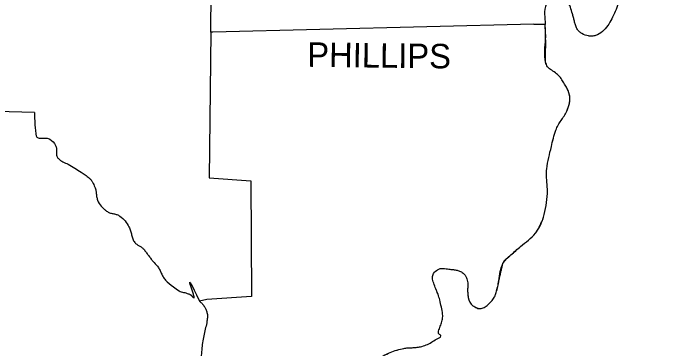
# Model space of a CAD drawing. Extents: x -33639 to 34530, y -17264 to 5867.
# Drawn here: x 3591 to 4217, y -9022 to -8698 of the extents above; entities that cross this region are included whole.
import ezdxf

# ---------------------------------------------------------------- set-up
doc = ezdxf.new("R2010")
doc.units = 0
for name, color, linetype in [('1', 7, 'Continuous'), ('2', 7, 'Continuous'), ('S_MISC_BOUNDARY', 7, 'Continuous')]:
    doc.layers.add(name, color=color, linetype=linetype)

msp = doc.modelspace()

# ---------------------------------------------------------------- linework, layer by layer
at = {"layer": '1'}
for points in [[(3782.6552624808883, -8716.897825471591), (3783.4401276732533, -8638.999955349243), (3748.7678360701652, -8634.046770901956), (3747.6671284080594, -8487.102296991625), (4217.118949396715, -8483.800173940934)], [(3612.280085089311, -8794.199736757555), (3404.2463354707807, -8788.696198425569), (3403.1456278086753, -8856.389720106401), (2982.1249442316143, -8858.04078158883)]]:
    msp.add_lwpolyline(points, dxfattribs=at)
for points in [[(4182.446657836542, -8616.985801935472), (4176.839301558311, -8626.142518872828), (4173.354075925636, -8629.968216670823), (4169.788519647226, -8632.946063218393), (4159.607709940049, -8631.900198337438), (4154.44128474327, -8628.02159438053), (4152.446856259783, -8625.615408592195), (4151.076489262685, -8623.03969419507), (4150.282008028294, -8616.424934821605), (4151.076489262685, -8609.831202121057), (4151.769537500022, -8606.379750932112), (4152.792009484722, -8602.937733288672), (4153.644663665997, -8599.502738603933), (4153.828258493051, -8596.072356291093), (4151.446090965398, -8591.104456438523), (4149.384231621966, -8589.015564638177), (4147.224012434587, -8587.266694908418), (4144.204489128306, -8586.327332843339), (4140.520775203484, -8586.809036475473), (4137.299322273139, -8588.48268852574), (4135.666581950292, -8591.119171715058), (4135.351394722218, -8595.382917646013), (4135.47434529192, -8599.651441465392), (4135.693414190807, -8603.91907265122), (4135.666581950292, -8608.180140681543), (4134.565874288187, -8624.690755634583), (4133.752950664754, -8630.63622680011), (4132.550640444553, -8636.557368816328), (4131.267171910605, -8645.409490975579), (4131.228518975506, -8646.882861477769), (4131.2637512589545, -8648.355970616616), (4133.887594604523, -8652.852424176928), (4136.332989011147, -8654.454435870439), (4138.968704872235, -8655.510570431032), (4143.361232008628, -8656.416362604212), (4147.778591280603, -8656.835997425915), (4152.193838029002, -8657.143272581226), (4156.58002759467, -8657.711985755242), (4162.965734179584, -8658.792122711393), (4166.118202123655, -8659.628099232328), (4169.238165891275, -8661.014108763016), (4174.468412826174, -8666.511939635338), (4175.971373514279, -8670.016217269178), (4176.943119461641, -8673.672246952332), (4177.608761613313, -8681.424923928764), (4176.3927656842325, -8689.082154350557), (4170.338873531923, -8703.941707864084), (4161.533212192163, -8716.049492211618), (4154.802060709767, -8719.895896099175), (4151.207795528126, -8720.602523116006), (4147.774366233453, -8720.452322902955), (4141.606295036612, -8718.156427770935), (4138.855503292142, -8716.05829140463), (4136.767289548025, -8713.29772308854), (4135.259610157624, -8709.733553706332), (4134.25795405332, -8706.134989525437), (4133.410258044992, -8702.540492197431), (4132.364458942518, -8698.98852337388), (4130.390589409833, -8692.638326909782), (4127.4112743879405, -8686.330385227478), (4125.205462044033, -8683.17621605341), (4122.843679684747, -8680.207531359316), (4118.055259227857, -8676.974369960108), (4115.508946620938, -8677.829001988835), (4112.959817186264, -8680.318819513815), (4110.481816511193, -8683.750592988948), (4109.292597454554, -8685.60307897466), (4108.148890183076, -8687.431092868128), (4105.482324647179, -8697.045322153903), (4105.9474748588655, -8706.693477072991), (4106.02163556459, -8709.30490390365)], [(3612.280085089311, -8794.199736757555), (3612.6459980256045, -8805.498155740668), (3613.095594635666, -8811.136475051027), (3613.4553670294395, -8813.951832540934), (3613.931146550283, -8816.764243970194), (3614.603640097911, -8818.08558149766), (3615.867074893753, -8818.786801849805), (3619.544067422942, -8819.049941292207), (3623.7167225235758, -8818.995762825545), (3625.5997355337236, -8819.30033579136), (3627.1396385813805, -8820.066366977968), (3632.6431769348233, -8826.120259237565), (3633.5182837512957, -8829.345532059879), (3633.4958907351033, -8832.984617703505), (3633.7350831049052, -8836.356058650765), (3635.3949460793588, -8838.778397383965), (3644.750961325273, -8844.281935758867), (3657.409099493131, -8851.986889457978), (3661.3475187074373, -8854.566361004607), (3663.2495329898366, -8855.972601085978), (3665.114053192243, -8857.490427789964), (3666.912376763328, -8859.397520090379), (3668.3419898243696, -8861.574758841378), (3669.533519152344, -8863.911247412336), (3670.6175915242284, -8866.29608917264), (3671.6601689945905, -8869.789880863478), (3672.154270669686, -8873.450711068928), (3672.705563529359, -8877.111530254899), (3673.9197145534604, -8880.6052888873), (3677.7374188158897, -8885.809518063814), (3680.1179015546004, -8887.990842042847), (3682.725375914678, -8889.961304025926), (3685.654498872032, -8891.328068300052), (3688.8388209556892, -8892.085290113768), (3691.993366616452, -8892.881226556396), (3694.8331603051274, -8894.364134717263), (3703.638821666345, -8904.820857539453), (3705.211449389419, -8908.482533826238), (3706.203943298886, -8912.412651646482), (3707.2897609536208, -8916.26176081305), (3709.1423599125, -8919.68041113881), (3711.155509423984, -8921.520623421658), (3713.5354468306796, -8922.99372230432), (3715.9202561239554, -8924.46122708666), (3717.948021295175, -8926.284657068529), (3720.172930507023, -8929.144806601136), (3722.3330942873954, -8932.073854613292), (3724.502136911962, -8934.997661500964), (3726.7536826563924, -8937.842087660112), (3731.1565133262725, -8942.795272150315), (3733.230450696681, -8945.98491689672), (3734.9033724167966, -8949.462593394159), (3736.629103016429, -8952.908732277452), (3738.861467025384, -8956.003764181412), (3746.5664207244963, -8962.608010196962), (3752.0699590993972, -8966.460487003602), (3754.171529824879, -8967.368614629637), (3756.4121827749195, -8967.94030184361), (3758.683139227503, -8968.460023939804), (3760.8756204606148, -8969.21225621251), (3763.8057252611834, -8970.656732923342), (3766.5940347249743, -8972.28962321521), (3771.8826971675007, -8976.366856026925), (3771.8826971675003, -8976.366856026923)]]:
    msp.add_spline(points, degree=3, dxfattribs=at)
at = {"layer": 'S_MISC_BOUNDARY'}
for p, q in [((4094.9403981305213, -8708.894892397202), (4106.02163556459, -8709.30490390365)), ((4106.02163556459, -8709.30490390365), (4094.9403981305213, -8708.894892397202))]:
    msp.add_line(p, q, dxfattribs=at)
for points in [[(4094.9403981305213, -8708.894892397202), (3784.540835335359, -8716.599846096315), (3782.6552624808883, -8716.897825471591), (3781.238712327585, -8857.490427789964), (3821.4145422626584, -8860.242196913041), (3821.9648961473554, -8971.964025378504), (3779.037296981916, -8974.715794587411), (3771.8826971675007, -8976.366856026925)], [(4094.9403981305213, -8708.894892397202), (3784.540835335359, -8716.599846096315), (3782.6552624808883, -8716.897825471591), (3781.238712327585, -8857.490427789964), (3821.4145422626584, -8860.242196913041), (3821.9648961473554, -8971.964025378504), (3779.037296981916, -8974.715794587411), (3771.8826971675, -8976.366856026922)]]:
    msp.add_lwpolyline(points, dxfattribs=at)
for points in [[(3865.99320288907, -9151.379375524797), (3867.4980547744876, -9147.874374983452), (3869.6105555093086, -9144.47649683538), (3875.899571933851, -9138.721237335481), (3880.8135846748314, -9136.348935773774), (3885.739313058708, -9134.996788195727), (3895.7123100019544, -9134.318406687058), (3899.839959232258, -9134.610621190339), (3903.9677854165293, -9135.171892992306), (3908.0955276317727, -9135.719187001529), (3912.2229249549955, -9135.969468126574), (3932.5860169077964, -9133.768052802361), (3939.797636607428, -9131.09677495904), (3943.123506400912, -9129.052991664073), (3946.34486273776, -9126.613452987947), (3950.65909664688, -9119.310034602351), (3950.8067185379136, -9115.17468012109), (3949.0966318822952, -9111.753899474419), (3945.9433337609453, -9108.80302774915), (3942.4726144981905, -9106.258528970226), (3938.736604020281, -9104.535477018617), (3934.7874322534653, -9104.048945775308), (3919.3775248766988, -9105.700007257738), (3903.417263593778, -9106.800714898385), (3895.6154853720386, -9105.634539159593), (3891.804334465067, -9104.19240677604), (3888.0073563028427, -9102.397884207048), (3877.5506333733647, -9093.041869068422), (3874.279775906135, -9085.173510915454), (3874.7988642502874, -9077.08160787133), (3876.1435894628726, -9073.610776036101), (3878.0124648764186, -9070.19105025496), (3880.4759553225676, -9067.46483411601), (3883.6045256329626, -9066.074531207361), (3885.5248064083, -9065.898640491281), (3887.45251670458, -9065.905292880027), (3891.3187711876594, -9066.31958270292), (3899.0144330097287, -9067.725592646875), (3910.5718634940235, -9069.927007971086), (3921.0285863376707, -9065.524177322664), (3928.733540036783, -9056.168162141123), (3937.5392013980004, -9046.2617931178), (3939.279349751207, -9043.417711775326), (3940.4859833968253, -9040.230734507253), (3941.7326990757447, -9037.032340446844), (3943.593093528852, -9034.15400872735), (3956.251231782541, -9025.898701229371), (3969.4597238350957, -9022.0462243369), (3973.414452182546, -9021.518812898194), (3977.4115903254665, -9021.325191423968), (3981.4228605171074, -9021.079321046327), (3985.4199850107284, -9020.395162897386), (3996.1110753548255, -9016.13839352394), (4000.9356181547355, -9013.205668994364), (4005.2327231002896, -9009.93843994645), (4005.197609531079, -9009.472691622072), (4004.4013825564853, -9008.983266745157), (4003.470472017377, -9008.42107463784), (4003.031307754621, -9007.73702462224), (4003.8208665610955, -9003.06332252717), (4005.362606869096, -8998.386437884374), (4006.70181682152, -8993.706839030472), (4006.8837845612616, -8989.024994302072), (4005.6561278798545, -8982.145199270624), (4004.132015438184, -8975.266148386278), (4002.4155369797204, -8969.79534489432), (4000.283165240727, -8964.433190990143), (3998.2865686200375, -8959.121565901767), (3996.977415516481, -8953.802348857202), (3998.1732886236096, -8949.603504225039), (4001.9306000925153, -8946.097395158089), (4004.6624243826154, -8944.950646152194), (4007.4315362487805, -8944.762386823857), (4012.9376767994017, -8945.547041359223), (4016.4440965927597, -8945.896448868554), (4019.9259854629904, -8946.34502339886), (4023.3534314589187, -8947.357726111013), (4026.6965226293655, -8949.399518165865), (4028.662449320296, -8951.482277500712), (4029.9242472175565, -8953.771031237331), (4031.099353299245, -8958.755533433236), (4031.222494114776, -8961.0920969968), (4031.1300157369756, -8963.435976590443), (4031.0222061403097, -8965.778638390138), (4031.099353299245, -8968.111548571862), (4033.300768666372, -8977.467563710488), (4039.9050146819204, -8982.97110208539), (4044.0860832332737, -8983.518702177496), (4048.160322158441, -8981.870394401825), (4051.661191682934, -8978.873916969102), (4054.7086362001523, -8975.63895027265), (4057.0961044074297, -8972.079994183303), (4058.617045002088, -8968.111548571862), (4061.3688142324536, -8956.55411806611), (4065.2212910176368, -8940.043503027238), (4072.926244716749, -8931.788195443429), (4082.282259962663, -8923.532887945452), (4096.591459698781, -8910.87474979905), (4104.296413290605, -8895.464842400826), (4106.84687790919, -8883.954113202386), (4108.148890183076, -8872.34998130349), (4108.102737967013, -8866.431359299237), (4107.626498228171, -8860.497021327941), (4107.27386600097, -8854.572859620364), (4107.598536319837, -8848.684766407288), (4112.001366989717, -8827.220966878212), (4116.404197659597, -8811.260705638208), (4118.531872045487, -8806.525237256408), (4121.351726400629, -8802.110190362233), (4124.311997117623, -8797.729981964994), (4126.860920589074, -8793.099029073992), (4129.61268973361, -8777.689121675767), (4126.120310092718, -8768.920323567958), (4123.551926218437, -8764.726733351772), (4120.807028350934, -8760.62815283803), (4116.998324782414, -8756.819163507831), (4112.402360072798, -8753.593945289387), (4108.431429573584, -8750.17094246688), (4106.497828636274, -8745.768599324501), (4106.497828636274, -8723.204092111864), (4106.02163556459, -8709.30490390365)], [(4103.473675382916, -8898.277130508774), (4104.296413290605, -8895.464842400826), (4105.761220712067, -8889.741818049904), (4106.84687790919, -8883.954113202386), (4108.148890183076, -8872.34998130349), (4108.102737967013, -8866.431359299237), (4107.626498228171, -8860.497021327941), (4107.27386600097, -8854.572859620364), (4107.598536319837, -8848.684766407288), (4112.001366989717, -8827.220966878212), (4116.404197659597, -8811.260705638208), (4118.531872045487, -8806.525237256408), (4121.351726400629, -8802.110190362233), (4124.311997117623, -8797.729981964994), (4126.860920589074, -8793.099029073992), (4129.475007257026, -8785.444568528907), (4129.924134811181, -8781.512814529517), (4129.61268973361, -8777.689121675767), (4128.249359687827, -8773.213239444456), (4126.120310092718, -8768.920323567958), (4123.551926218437, -8764.726733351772), (4120.807028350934, -8760.62815283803), (4116.998324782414, -8756.819163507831), (4112.402360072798, -8753.593945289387), (4108.431429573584, -8750.17094246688), (4106.497828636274, -8745.768599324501), (4106.4216027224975, -8740.127449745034), (4106.493967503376, -8734.485224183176), (4106.568262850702, -8728.84355938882), (4106.497828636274, -8723.204092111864), (4106.02163556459, -8709.30490390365)], [(4002.1590626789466, -8969.131808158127), (4000.283165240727, -8964.433190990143), (3998.2865686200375, -8959.121565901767), (3996.977415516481, -8953.802348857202), (3998.1732886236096, -8949.603504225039), (4001.9306000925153, -8946.097395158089), (4004.6624243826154, -8944.950646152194), (4007.4315362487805, -8944.762386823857), (4012.9376767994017, -8945.547041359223), (4016.4440965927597, -8945.896448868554), (4019.9259854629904, -8946.34502339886), (4023.3534314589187, -8947.357726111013), (4026.6965226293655, -8949.399518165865), (4028.662449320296, -8951.482277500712), (4029.9242472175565, -8953.771031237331), (4031.099353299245, -8958.755533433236), (4031.222494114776, -8961.0920969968), (4031.1300157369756, -8963.435976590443), (4031.0222061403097, -8965.778638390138), (4031.099353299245, -8968.111548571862), (4031.6919003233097, -8972.840224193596), (4032.3327610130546, -8975.16213644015), (4033.300768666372, -8977.467563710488), (4036.0799892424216, -8980.778076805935), (4037.8971230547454, -8981.968272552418), (4039.9050146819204, -8982.97110208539), (4042.0024122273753, -8983.579835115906), (4044.0860832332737, -8983.518702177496), (4048.160322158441, -8981.870394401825), (4051.661191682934, -8978.873916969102), (4054.7086362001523, -8975.63895027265), (4057.0961044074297, -8972.079994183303), (4058.617045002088, -8968.111548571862), (4061.3688142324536, -8956.55411806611), (4063.243446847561, -8948.293143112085), (4064.1946518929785, -8944.163363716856), (4064.695440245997, -8942.101750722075), (4065.2212910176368, -8940.043503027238), (4068.3754855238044, -8935.48055522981), (4072.926244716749, -8931.788195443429), (4082.282259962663, -8923.532887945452), (4096.591459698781, -8910.87474979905), (4103.473675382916, -8898.277130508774)], [(3875.073105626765, -9076.245004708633), (3876.1435894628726, -9073.610776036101), (3878.0124648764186, -9070.19105025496), (3880.4759553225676, -9067.46483411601), (3883.6045256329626, -9066.074531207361), (3885.5248064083, -9065.898640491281), (3887.45251670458, -9065.905292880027), (3891.3187711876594, -9066.31958270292), (3899.0144330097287, -9067.725592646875), (3910.5718634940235, -9069.927007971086), (3916.1613720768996, -9069.048075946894), (3918.7564375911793, -9067.512435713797), (3921.0285863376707, -9065.524177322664), (3923.1002419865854, -9063.20100068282), (3924.991004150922, -9060.84081452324), (3928.733540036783, -9056.168162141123), (3933.155005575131, -9051.246405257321), (3937.5392013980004, -9046.2617931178), (3939.279349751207, -9043.417711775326), (3940.4859833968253, -9040.230734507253), (3941.7326990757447, -9037.032340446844), (3943.593093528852, -9034.15400872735), (3946.42538606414, -9031.500881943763), (3949.4874676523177, -9029.279500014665), (3956.251231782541, -9025.898701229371), (3969.4597238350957, -9022.0462243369), (3973.414452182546, -9021.518812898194), (3977.4115903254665, -9021.325191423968), (3981.4228605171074, -9021.079321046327), (3985.4199850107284, -9020.395162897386), (3996.1110753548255, -9016.13839352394), (4000.9356181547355, -9013.205668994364), (4005.2327231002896, -9009.93843994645), (4005.197609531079, -9009.472691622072), (4004.4013825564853, -9008.983266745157), (4003.470472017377, -9008.42107463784), (4003.031307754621, -9007.73702462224), (4003.8208665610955, -9003.06332252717), (4005.362606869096, -8998.386437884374), (4006.70181682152, -8993.706839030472), (4006.8837845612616, -8989.024994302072), (4005.6561278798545, -8982.145199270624), (4004.132015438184, -8975.266148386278), (4002.4155369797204, -8969.79534489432), (4002.1590626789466, -8969.131808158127)], [(3771.8826971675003, -8976.366856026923), (3774.312545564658, -8978.812004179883), (3776.3758064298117, -8981.433854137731), (3777.9811626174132, -8984.273974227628), (3779.037296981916, -8987.373932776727), (3779.474904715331, -8991.511836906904), (3779.037296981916, -8995.629240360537), (3776.2855278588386, -9008.287378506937), (3774.0841125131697, -9021.49587058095), (3772.9834048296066, -9036.355424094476), (3771.8826971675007, -9049.563916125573), (3772.4834405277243, -9052.441956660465), (3774.1246479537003, -9055.151272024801), (3775.883176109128, -9057.818678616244), (3776.8358816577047, -9060.57099283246), (3776.8793758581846, -9064.625736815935), (3776.3868478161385, -9068.825261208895), (3774.0841125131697, -9077.08160787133), (3772.742481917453, -9079.346469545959), (3770.9895298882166, -9081.413034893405), (3769.4079845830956, -9083.515302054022), (3768.5805741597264, -9085.887269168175), (3768.372941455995, -9088.91018884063), (3768.279944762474, -9091.940368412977), (3768.199674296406, -9094.97094446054), (3768.0302202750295, -9097.995053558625), (3766.379158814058, -9116.156730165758), (3764.177743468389, -9126.613452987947), (3762.0874608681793, -9135.22755323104), (3760.806169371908, -9139.475537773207), (3760.059601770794, -9141.581573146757), (3759.224558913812, -9143.674421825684), (3756.133646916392, -9148.419548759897), (3752.0699590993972, -9152.48008320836)], [(3771.8826971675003, -8976.366856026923), (3774.312545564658, -8978.812004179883), (3776.3758064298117, -8981.433854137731), (3777.9811626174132, -8984.273974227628), (3779.037296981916, -8987.373932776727), (3779.474904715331, -8991.511836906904), (3779.037296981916, -8995.629240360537), (3776.2855278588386, -9008.287378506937), (3774.0841125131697, -9021.49587058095), (3772.9834048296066, -9036.355424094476), (3771.8826971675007, -9049.563916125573), (3772.4834405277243, -9052.441956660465), (3774.1246479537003, -9055.151272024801), (3775.883176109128, -9057.818678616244), (3776.8358816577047, -9060.57099283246), (3776.8793758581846, -9064.625736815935), (3776.3868478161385, -9068.825261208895), (3774.0841125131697, -9077.08160787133), (3772.742481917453, -9079.346469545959), (3770.9895298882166, -9081.413034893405), (3769.4079845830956, -9083.515302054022), (3768.5805741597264, -9085.887269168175), (3768.372941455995, -9088.91018884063), (3768.279944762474, -9091.940368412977), (3768.199674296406, -9094.97094446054), (3768.0302202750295, -9097.995053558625), (3766.379158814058, -9116.156730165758), (3764.177743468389, -9126.613452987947), (3762.0874608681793, -9135.22755323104), (3760.806169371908, -9139.475537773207), (3760.059601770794, -9141.581573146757), (3759.224558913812, -9143.674421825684), (3756.133646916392, -9148.419548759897), (3752.0699590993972, -9152.48008320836)]]:
    msp.add_spline(points, degree=3, dxfattribs=at)

# ---------------------------------------------------------------- texts
at = {"layer": '2'}
msp.add_text('PHILLIPS', height=23.659711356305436, rotation=359.31793888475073, dxfattribs=at).set_placement((3875.899571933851, -8750.17143001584))

doc.saveas('drawing.dxf')
